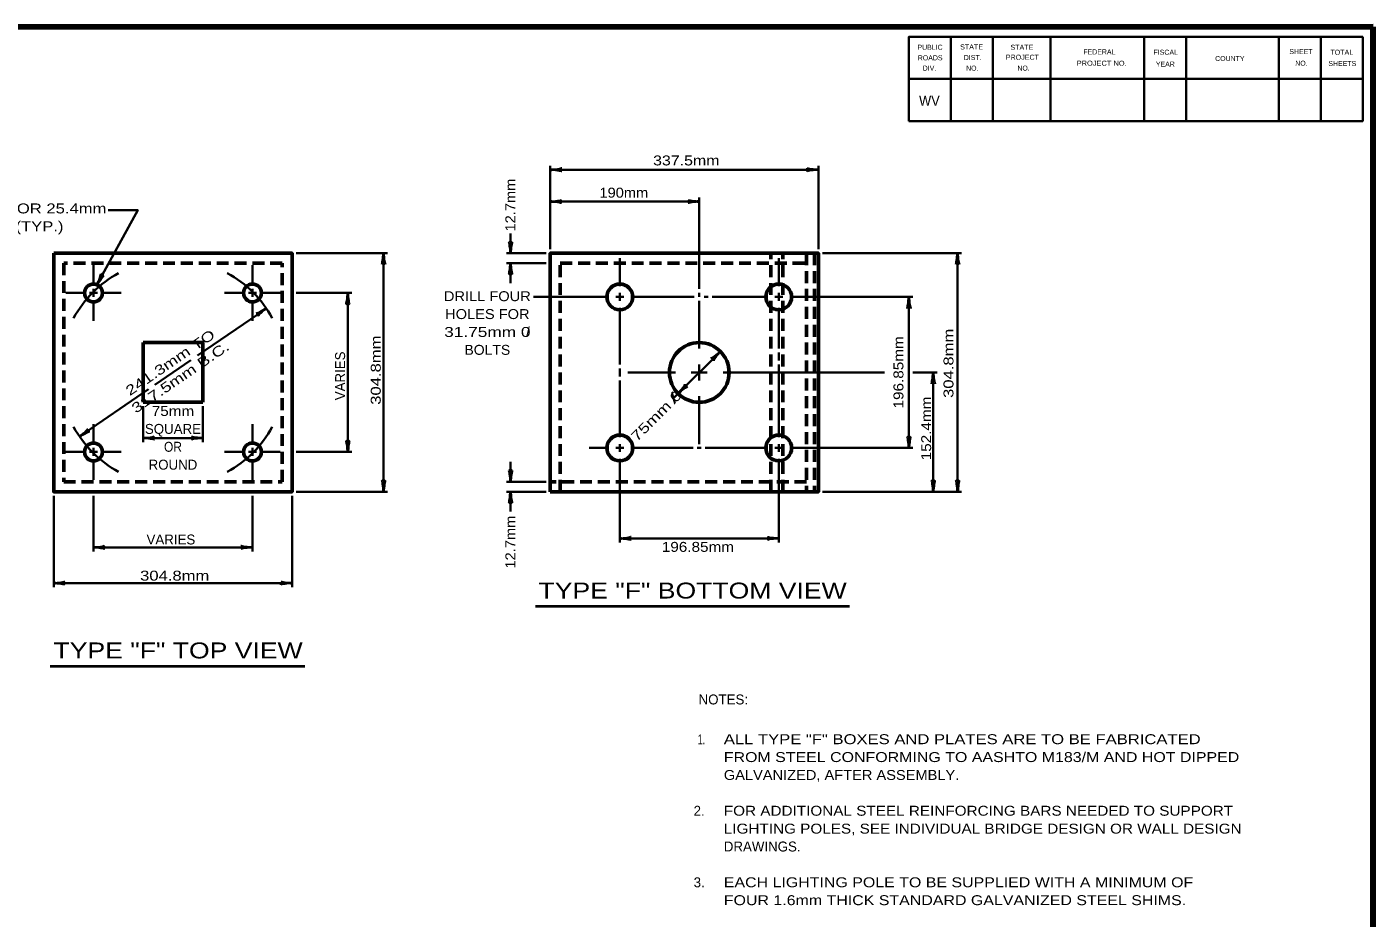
# Model space of a CAD drawing. Extents: x -40 to 816, y -10 to 535.
# Drawn here: x 402.8 to 809.3, y 259.1 to 528.1 of the extents above; entities that cross this region are included whole.
import ezdxf
from ezdxf.enums import TextEntityAlignment as Align

# ---------------------------------------------------------------- set-up
doc = ezdxf.new("R2010")
doc.units = 0
doc.header["$LTSCALE"] = 1.2
doc.linetypes.add('MEDIUM_DASHED', pattern=[4.5, 3, -1.5])
doc.layers.add('1', color=7, linetype='Continuous', lineweight=53)
doc.layers.add('61', color=7, linetype='Continuous', lineweight=35)

msp = doc.modelspace()

# ---------------------------------------------------------------- linework, layer by layer
at = {"layer": '1', "lineweight": 158}
msp.add_line((809.296, 2.017), (809.296, 528.117), dxfattribs=at)
at = {"layer": '1', "lineweight": 13}
msp.add_line((809.296, 2.017), (809.296, 528.117), dxfattribs=at)
at = {"layer": '1', "lineweight": 35}
for p, q in [((560.812, 461.005), (560.812, 486.205)), ((560.812, 485.005), (641.812, 485.005)), ((641.812, 461.005), (641.812, 486.205)), ((605.812, 449.005), (605.812, 476.605)), ((605.812, 475.405), (560.812, 475.405)), ((548.812, 459.805), (548.812, 465.805)), ((484.065, 459.805), (511.665, 459.805)), ((510.465, 459.805), (510.465, 387.805)), ((559.612, 459.805), (547.612, 459.805)), ((643.012, 459.805), (685.012, 459.805)), ((683.812, 459.805), (683.812, 387.805)), ((422.865, 450.205), (422.865, 456.205)), ((470.865, 450.205), (470.865, 456.205)), ((559.612, 456.805), (547.612, 456.805)), ((548.812, 456.805), (548.812, 450.805)), ((581.812, 449.905), (581.812, 458.305)), ((629.812, 449.905), (629.812, 458.305)), ((420.465, 447.805), (414.465, 447.805)), ((424.065, 447.805), (421.665, 447.805)), ((422.865, 449.005), (422.865, 446.605)), ((425.265, 447.805), (431.265, 447.805)), ((468.465, 447.805), (462.465, 447.805)), ((472.065, 447.805), (469.665, 447.805)), ((470.865, 446.605), (470.865, 449.005)), ((473.265, 447.805), (479.265, 447.805)), ((484.065, 447.805), (500.865, 447.805)), ((499.665, 447.805), (499.665, 399.805)), ((581.812, 445.405), (581.812, 447.805)), ((605.812, 446.605), (605.812, 447.805)), ((629.812, 445.405), (629.812, 447.805)), ((422.865, 445.405), (422.865, 439.405)), ((454.286, 428.897), (475.065, 443.155)), ((470.865, 445.405), (470.865, 439.405)), ((578.512, 446.605), (555.712, 446.605)), ((580.612, 446.605), (583.012, 446.605)), ((581.812, 443.305), (581.812, 426.205)), ((585.112, 446.605), (604.312, 446.605)), ((605.812, 431.005), (605.812, 445.405)), ((608.512, 446.605), (607.312, 446.605)), ((626.512, 446.605), (609.712, 446.605)), ((628.612, 446.605), (631.012, 446.605)), ((629.812, 443.305), (629.812, 430.989)), ((633.112, 446.605), (670.312, 446.605)), ((669.112, 446.605), (669.112, 401.005)), ((441.423, 420.071), (452.307, 427.539)), ((598.126, 416.119), (612.176, 430.169)), ((629.812, 429.789), (629.812, 427.389)), ((581.812, 425.005), (581.812, 422.605)), ((598.612, 423.805), (584.212, 423.805)), ((603.412, 423.805), (608.212, 423.805)), ((605.812, 421.405), (605.812, 426.205)), ((613.012, 423.805), (661.774, 423.805)), ((629.812, 426.189), (629.812, 404.305)), ((670.312, 423.805), (677.662, 423.805)), ((676.462, 387.805), (676.462, 423.805)), ((581.812, 421.405), (581.812, 404.305)), ((418.665, 404.456), (439.444, 418.713)), ((605.812, 416.605), (605.812, 402.205)), ((437.865, 413.605), (437.865, 402.805)), ((455.865, 413.605), (455.865, 402.805)), ((422.865, 402.205), (422.865, 408.205)), ((470.865, 402.205), (470.865, 408.205)), ((437.865, 404.005), (455.865, 404.005)), ((420.465, 399.805), (414.465, 399.805)), ((421.665, 399.805), (424.065, 399.805)), ((422.865, 401.005), (422.865, 398.605)), ((425.265, 399.805), (431.265, 399.805)), ((468.465, 399.805), (462.465, 399.805)), ((469.665, 399.805), (472.065, 399.805)), ((470.865, 398.605), (470.865, 401.005)), ((473.265, 399.805), (479.265, 399.805)), ((484.065, 399.805), (500.865, 399.805)), ((578.512, 401.005), (572.512, 401.005)), ((580.612, 401.005), (583.012, 401.005)), ((581.812, 399.805), (581.812, 402.205)), ((585.112, 401.005), (604.012, 401.005)), ((605.212, 401.005), (606.412, 401.005)), ((607.612, 401.005), (626.512, 401.005)), ((628.612, 401.005), (631.012, 401.005)), ((629.812, 399.805), (629.812, 402.205)), ((633.112, 401.005), (670.312, 401.005)), ((422.865, 397.405), (422.865, 391.405)), ((470.865, 397.405), (470.865, 391.405)), ((548.812, 390.805), (548.812, 396.805)), ((581.812, 397.705), (581.812, 372.505)), ((629.812, 397.705), (629.812, 372.505)), ((559.612, 390.805), (547.612, 390.805)), ((410.865, 386.605), (410.865, 359.005)), ((422.865, 386.605), (422.865, 369.805)), ((470.865, 386.605), (470.865, 369.805)), ((482.865, 386.605), (482.865, 359.005)), ((484.065, 387.805), (511.665, 387.805)), ((559.612, 387.805), (547.612, 387.805)), ((548.812, 387.805), (548.812, 381.805)), ((643.012, 387.805), (685.012, 387.805)), ((422.865, 371.005), (470.865, 371.005)), ((581.812, 373.705), (629.812, 373.705)), ((410.865, 360.205), (482.865, 360.205))]:
    msp.add_line(p, q, dxfattribs=at)
at = {"layer": '1', "linetype": 'MEDIUM_DASHED'}
for p, q in [((627.412, 387.805), (627.412, 459.805)), ((631.012, 387.805), (631.012, 459.805)), ((638.212, 459.805), (638.212, 387.805)), ((640.612, 459.805), (640.612, 387.805)), ((413.865, 456.805), (413.865, 390.805)), ((479.865, 456.805), (413.865, 456.805)), ((479.865, 390.805), (479.865, 456.805)), ((563.812, 456.805), (638.212, 456.805)), ((563.812, 387.805), (563.812, 456.805)), ((413.865, 390.805), (479.865, 390.805)), ((638.212, 390.805), (560.812, 390.805))]:
    msp.add_line(p, q, dxfattribs=at)
at = {"layer": '1'}
for p, q in [((437.865, 432.805), (437.865, 414.805)), ((437.865, 414.805), (455.865, 414.805))]:
    msp.add_line(p, q, dxfattribs=at)
at = {"layer": '1', "lineweight": 40}
for p, q in [((556.378, 353.246), (651.194, 353.246)), ((409.787, 335.165), (486.676, 335.165))]:
    msp.add_line(p, q, dxfattribs=at)
at = {"layer": '1', "lineweight": 158}
msp.add_lwpolyline([(809.296, 528.117), (17.596, 528.017), (17.696, 2.017)], dxfattribs=at)
at = {"layer": '1', "lineweight": 35}
msp.add_lwpolyline([(423.918, 450.292), (436.236, 472.804), (427.325, 472.804)], dxfattribs=at)
at = {"layer": '1'}
for points in [[(410.865, 459.805), (410.865, 387.805), (482.865, 387.805), (482.865, 459.805)], [(560.812, 387.805), (560.812, 459.805), (641.812, 459.805), (641.812, 387.805)]]:
    msp.add_lwpolyline(points, close=True, dxfattribs=at)
msp.add_lwpolyline([(455.865, 414.805), (455.865, 432.805), (437.865, 432.805)], dxfattribs=at)
for centre, radius in [((422.865, 447.805), 2.7), ((470.865, 447.805), 2.7), ((581.812, 446.605), 3.9), ((629.812, 446.605), 3.9), ((605.812, 423.805), 9), ((422.865, 399.805), 2.7), ((470.865, 399.805), 2.7), ((581.812, 401.005), 3.9), ((629.812, 401.005), 3.9)]:
    msp.add_circle(centre, radius, dxfattribs=at)
at = {"layer": '1', "lineweight": 35}
for start, end in [(118.69441, 151.30559), (28.69441, 61.30559), (208.69441, 241.30559), (298.69441, 331.30559)]:
    msp.add_arc((446.865, 423.805), 34.2, start, end, dxfattribs=at)
at = {"layer": '1', "lineweight": 40}
for centre, major_axis, ratio, start_param, end_param in [((562.157, 484.751), (-2.108, 0.211), 0.07063, 3.1407148, 5.41811), ((562.122, 485.337), (-2.143, -0.187), 0.122415, 0.8963533, 3.1415927), ((640.503, 484.674), (2.143, 0.187), 0.122415, 0.8963533, 3.1415927), ((640.468, 485.259), (2.108, -0.211), 0.07063, 3.1407148, 5.41811), ((562.122, 475.737), (-2.143, -0.187), 0.122415, 0.8963533, 3.1415927), ((562.122, 475.737), (-2.143, -0.187), 0.122415, 0.8963533, 3.1415927), ((604.468, 475.659), (2.108, -0.211), 0.07063, 3.1407148, 5.41811), ((562.157, 475.151), (-2.108, 0.211), 0.07063, 3.1407148, 5.41811), ((562.157, 475.151), (-2.108, 0.211), 0.07063, 3.1407148, 5.41811), ((604.503, 475.074), (2.143, 0.187), 0.122415, 0.8963533, 3.1415927), ((510.211, 458.461), (0.211, 2.108), 0.07063, 3.1407148, 5.41811), ((510.211, 458.461), (0.211, 2.108), 0.07063, 3.1407148, 5.41811), ((510.797, 458.496), (-0.187, 2.143), 0.122415, 0.8963533, 3.1415927), ((510.797, 458.496), (-0.187, 2.143), 0.122415, 0.8963533, 3.1415927), ((548.481, 461.115), (0.187, -2.143), 0.122415, 0.8963533, 3.1415927), ((548.481, 461.115), (0.187, -2.143), 0.122415, 0.8963533, 3.1415927), ((549.066, 461.15), (-0.211, -2.108), 0.07063, 3.1407148, 5.41811), ((549.066, 461.15), (-0.211, -2.108), 0.07063, 3.1407148, 5.41811), ((683.558, 458.461), (0.211, 2.108), 0.07063, 3.1407148, 5.41811), ((683.558, 458.461), (0.211, 2.108), 0.07063, 3.1407148, 5.41811), ((684.144, 458.496), (-0.187, 2.143), 0.122415, 0.8963533, 3.1415927), ((684.144, 458.496), (-0.187, 2.143), 0.122415, 0.8963533, 3.1415927), ((548.558, 455.461), (0.211, 2.108), 0.07063, 3.1407148, 5.41811), ((548.558, 455.461), (0.211, 2.108), 0.07063, 3.1407148, 5.41811), ((549.144, 455.496), (-0.187, 2.143), 0.122415, 0.8963533, 3.1415927), ((549.144, 455.496), (-0.187, 2.143), 0.122415, 0.8963533, 3.1415927), ((424.256, 451.599), (-0.864, -1.97), 0.122415, 0.8963533, 3.1415927), ((424.786, 451.349), (1.197, 1.748), 0.07063, 6.2823074, 8.5597026), ((499.411, 446.461), (0.211, 2.108), 0.07063, 3.1407148, 5.41811), ((499.411, 446.461), (0.211, 2.108), 0.07063, 3.1407148, 5.41811), ((499.997, 446.496), (-0.187, 2.143), 0.122415, 0.8963533, 3.1415927), ((499.997, 446.496), (-0.187, 2.143), 0.122415, 0.8963533, 3.1415927), ((473.813, 442.603), (1.857, 1.019), 0.07063, 3.1407148, 5.41811), ((474.173, 442.14), (1.661, 1.367), 0.122415, 0.8963533, 3.1415927), ((668.858, 445.261), (0.211, 2.108), 0.07063, 3.1407148, 5.41811), ((668.858, 445.261), (0.211, 2.108), 0.07063, 3.1407148, 5.41811), ((669.444, 445.296), (-0.187, 2.143), 0.122415, 0.8963533, 3.1415927), ((669.444, 445.296), (-0.187, 2.143), 0.122415, 0.8963533, 3.1415927), ((611.046, 429.398), (1.639, 1.341), 0.07063, 3.1407148, 5.41811), ((611.046, 429.398), (1.639, 1.341), 0.07063, 3.1407148, 5.41811), ((611.485, 429.009), (1.383, 1.648), 0.122415, 0.8963533, 3.1415927), ((611.485, 429.009), (1.383, 1.648), 0.122415, 0.8963533, 3.1415927), ((676.208, 422.461), (0.211, 2.108), 0.07063, 3.1407148, 5.41811), ((676.208, 422.461), (0.211, 2.108), 0.07063, 3.1407148, 5.41811), ((676.794, 422.496), (-0.187, 2.143), 0.122415, 0.8963533, 3.1415927), ((676.794, 422.496), (-0.187, 2.143), 0.122415, 0.8963533, 3.1415927), ((600.14, 418.602), (-1.383, -1.648), 0.122415, 0.8963533, 3.1415927), ((600.579, 418.213), (-1.639, -1.341), 0.07063, 3.1407148, 5.41811), ((419.557, 405.47), (-1.661, -1.367), 0.122415, 0.8963533, 3.1415927), ((419.918, 405.007), (-1.857, -1.019), 0.07063, 3.1407148, 5.41811), ((439.21, 403.751), (-2.108, 0.211), 0.07063, 3.1407148, 5.41811), ((439.21, 403.751), (-2.108, 0.211), 0.07063, 3.1407148, 5.41811), ((439.175, 404.337), (-2.143, -0.187), 0.122415, 0.8963533, 3.1415927), ((439.175, 404.337), (-2.143, -0.187), 0.122415, 0.8963533, 3.1415927), ((454.556, 403.674), (2.143, 0.187), 0.122415, 0.8963533, 3.1415927), ((454.521, 404.259), (2.108, -0.211), 0.07063, 3.1407148, 5.41811), ((499.334, 401.115), (0.187, -2.143), 0.122415, 0.8963533, 3.1415927), ((499.334, 401.115), (0.187, -2.143), 0.122415, 0.8963533, 3.1415927), ((499.919, 401.15), (-0.211, -2.108), 0.07063, 3.1407148, 5.41811), ((499.919, 401.15), (-0.211, -2.108), 0.07063, 3.1407148, 5.41811), ((668.781, 402.315), (0.187, -2.143), 0.122415, 0.8963533, 3.1415927), ((668.781, 402.315), (0.187, -2.143), 0.122415, 0.8963533, 3.1415927), ((669.366, 402.35), (-0.211, -2.108), 0.07063, 3.1407148, 5.41811), ((669.366, 402.35), (-0.211, -2.108), 0.07063, 3.1407148, 5.41811), ((510.134, 389.115), (0.187, -2.143), 0.122415, 0.8963533, 3.1415927), ((510.719, 389.15), (-0.211, -2.108), 0.07063, 3.1407148, 5.41811), ((548.481, 392.115), (0.187, -2.143), 0.122415, 0.8963533, 3.1415927), ((548.481, 392.115), (0.187, -2.143), 0.122415, 0.8963533, 3.1415927), ((549.066, 392.15), (-0.211, -2.108), 0.07063, 3.1407148, 5.41811), ((549.066, 392.15), (-0.211, -2.108), 0.07063, 3.1407148, 5.41811), ((676.131, 389.115), (0.187, -2.143), 0.122415, 0.8963533, 3.1415927), ((676.131, 389.115), (0.187, -2.143), 0.122415, 0.8963533, 3.1415927), ((676.716, 389.15), (-0.211, -2.108), 0.07063, 3.1407148, 5.41811), ((676.716, 389.15), (-0.211, -2.108), 0.07063, 3.1407148, 5.41811), ((683.481, 389.115), (0.187, -2.143), 0.122415, 0.8963533, 3.1415927), ((684.066, 389.15), (-0.211, -2.108), 0.07063, 3.1407148, 5.41811), ((548.558, 386.461), (0.211, 2.108), 0.07063, 3.1407148, 5.41811), ((549.144, 386.496), (-0.187, 2.143), 0.122415, 0.8963533, 3.1415927), ((583.122, 374.037), (-2.143, -0.187), 0.122415, 0.8963533, 3.1415927), ((583.122, 374.037), (-2.143, -0.187), 0.122415, 0.8963533, 3.1415927), ((628.468, 373.959), (2.108, -0.211), 0.07063, 3.1407148, 5.41811), ((424.21, 370.751), (-2.108, 0.211), 0.07063, 3.1407148, 5.41811), ((424.21, 370.751), (-2.108, 0.211), 0.07063, 3.1407148, 5.41811), ((424.175, 371.337), (-2.143, -0.187), 0.122415, 0.8963533, 3.1415927), ((424.175, 371.337), (-2.143, -0.187), 0.122415, 0.8963533, 3.1415927), ((469.556, 370.674), (2.143, 0.187), 0.122415, 0.8963533, 3.1415927), ((469.556, 370.674), (2.143, 0.187), 0.122415, 0.8963533, 3.1415927), ((469.521, 371.259), (2.108, -0.211), 0.07063, 3.1407148, 5.41811), ((469.521, 371.259), (2.108, -0.211), 0.07063, 3.1407148, 5.41811), ((583.157, 373.451), (-2.108, 0.211), 0.07063, 3.1407148, 5.41811), ((583.157, 373.451), (-2.108, 0.211), 0.07063, 3.1407148, 5.41811), ((628.503, 373.374), (2.143, 0.187), 0.122415, 0.8963533, 3.1415927), ((412.21, 359.951), (-2.108, 0.211), 0.07063, 3.1407148, 5.41811), ((412.175, 360.537), (-2.143, -0.187), 0.122415, 0.8963533, 3.1415927), ((481.556, 359.874), (2.143, 0.187), 0.122415, 0.8963533, 3.1415927), ((481.556, 359.874), (2.143, 0.187), 0.122415, 0.8963533, 3.1415927), ((481.521, 360.459), (2.108, -0.211), 0.07063, 3.1407148, 5.41811), ((481.521, 360.459), (2.108, -0.211), 0.07063, 3.1407148, 5.41811)]:
    msp.add_ellipse(centre, major_axis=major_axis, ratio=ratio, start_param=start_param, end_param=end_param, dxfattribs=at)
at = {"layer": '61'}
for p, q in [((681.796, 525.117), (681.796, 499.717)), ((694.496, 525.117), (694.496, 499.717)), ((711.896, 525.117), (711.896, 499.717)), ((740.196, 525.117), (740.196, 499.717)), ((752.896, 525.117), (752.896, 499.717)), ((780.796, 525.117), (780.796, 499.717)), ((793.496, 525.117), (793.496, 499.717)), ((806.196, 512.417), (669.096, 512.417))]:
    msp.add_line(p, q, dxfattribs=at)
for points in [[(806.196, 525.117), (669.096, 525.117), (669.096, 499.717)], [(806.196, 525.117), (806.196, 499.717), (669.096, 499.717)]]:
    msp.add_lwpolyline(points, dxfattribs=at)

# ---------------------------------------------------------------- texts
at = {"layer": '1'}
for s, height, width, p in [('WV', 3.048, 0.95, (672.196, 504.317)), ('ALL TYPE "F" BOXES AND PLATES ARE TO BE FABRICATED', 3, 1.25, (613.222, 311.591)), ('FROM STEEL CONFORMING TO AASHTO M183/M AND HOT DIPPED', 3, 1.2, (613.222, 306.191)), ('GALVANIZED, AFTER ASSEMBLY.', 3, 1.1, (613.222, 300.791)), ('FOR ADDITIONAL STEEL REINFORCING BARS NEEDED TO SUPPORT', 3, 1.15, (613.222, 289.991)), ('LIGHTING POLES, SEE INDIVIDUAL BRIDGE DESIGN OR WALL DESIGN', 3, 1.15, (613.222, 284.591)), ('EACH LIGHTING POLE TO BE SUPPLIED WITH A MINIMUM OF', 3, 1.2, (613.222, 268.391)), ('FOUR 1.6mm THICK STANDARD GALVANIZED STEEL SHIMS.', 3, 1.2, (613.222, 262.991))]:
    msp.add_text(s, height=height, dxfattribs=dict(at, width=width)).set_placement(p)
for s, height, width, p in [('337.5mm', 3, 1.2, (601.894, 486.307)), ('190mm', 3, 1.1, (583.027, 476.579)), ('DRILL (AND TAP) FOR 25.4mm', 3, 1.25, (390.674, 471.821)), ('STEEL BOLT (TYP.)', 3, 1.25, (390.674, 466.421)), ('DRILL FOUR', 3, 1.1, (541.805, 445.33)), ('HOLES FOR', 3, 1.1, (541.805, 439.93)), ('31.75mm 0', 3, 1.3, (541.805, 434.53)), ('BOLTS', 3, 1.05, (541.805, 429.13)), ('75mm', 3, 1.15, (446.866, 410.664)), ('OR', 3, 0.9, (446.866, 399.864)), ('196.85mm', 3, 1.15, (605.396, 369.651)), ('304.8mm', 3, 1.25, (447.393, 360.966)), ('TYPE "F" BOTTOM VIEW', 4.8, 1.25, (603.797, 355.565)), ('TYPE "F" TOP VIEW', 4.8, 1.25, (448.413, 337.484)), ('1.', 3, 0.65, (606.461, 311.547))]:
    msp.add_text(s, height=height, dxfattribs=dict(at, width=width)).set_placement(p, align=Align.CENTER)
for s, rotation, width, p in [('12.7mm', 90, 1.1, (550.255, 474.328)), ('241.3mm TO', 34.456, 1.35, (446.872, 425.577)), ('304.8mm', 90, 1.25, (682.57, 426.565)), ('317.5mm B.C.', 34.456, 1.35, (449.927, 421.124)), ('304.8mm', 90, 1.25, (509.615, 424.501)), ('196.85mm', 90, 1.15, (667.461, 423.834)), ('75mm 0', 45, 1.35, (593.894, 409.676)), ('/', 45, 2.3, (599.103, 415.028)), ('152.4mm', 90, 1.15, (675.835, 406.899)), ('12.7mm', 90, 1.1, (550.255, 372.584))]:
    msp.add_text(s, height=3, rotation=rotation, dxfattribs=dict(at, width=width)).set_placement(p, align=Align.CENTER)
for s, p in [('/', (554.076, 434.599)), ('SQUARE', (446.866, 405.264)), ('ROUND', (446.866, 394.464)), ('VARIES', (446.244, 371.879)), ('NOTES:', (613.074, 323.586)), ('2.', (605.77, 289.972)), ('3.', (605.786, 268.376))]:
    msp.add_text(s, height=3, dxfattribs=at).set_placement(p, align=Align.CENTER)
msp.add_text('VARIES', height=3, rotation=90, dxfattribs=at).set_placement((498.849, 422.777), align=Align.CENTER)
msp.add_text('DRAWINGS.', height=3, dxfattribs=at).set_placement((613.222, 279.191))
at = {"layer": '61'}
for s, height, rotation, p in [('PUBLIC', 1.525, 0.033, (671.696, 521.217)), ('FEDERAL', 1.523, 0.007, (721.796, 519.817)), ('FISCAL', 1.525, 359.942, (742.996, 519.717)), ('SHEET', 1.525, 0.059, (783.996, 519.917)), ('ROADS', 1.525, 0.124, (671.796, 518.017)), ('DIV.', 1.525, 359.932, (673.296, 514.917)), ('DIST.', 1.525, 0.056, (685.696, 518.117)), ('YEAR', 1.523, 0.105, (743.696, 516.117)), ('COUNTY', 1.523, 0.069, (761.596, 517.817)), ('SHEETS', 1.523, 359.959, (795.796, 516.317))]:
    msp.add_text(s, height=height, rotation=rotation, dxfattribs=at).set_placement(p)
for s, rotation, width, p in [('STATE', 0.059, 1.05, (684.596, 521.317)), ('STATE', 0.059, 1.05, (699.796, 521.217)), ('TOTAL', 359.926, 1.05, (796.396, 519.717)), ('NO.', 359.852, 0.9, (686.396, 514.917)), ('PROJECT', 359.908, 1.05, (698.396, 518.217)), ('NO.', 0.225, 0.9, (701.896, 514.917)), ('PROJECT NO.', 359.922, 1.1, (719.796, 516.417)), ('NO.', 359.852, 0.9, (785.796, 516.417))]:
    msp.add_text(s, height=1.525, rotation=rotation, dxfattribs=dict(at, width=width)).set_placement(p)

doc.saveas('drawing.dxf')
